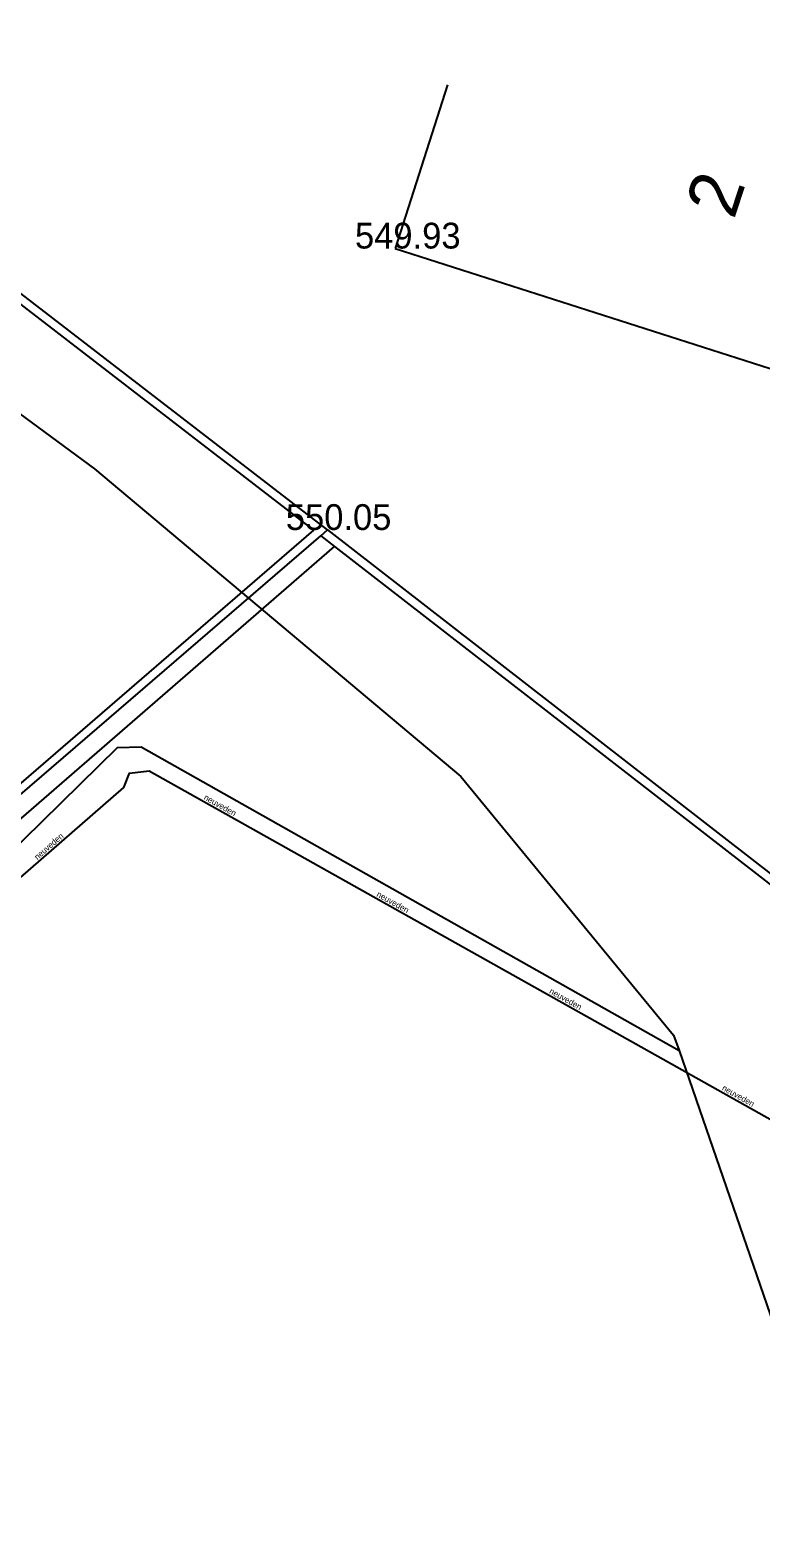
# Model space of a CAD drawing. Extents: x -669995 to -669686, y -1125551 to -1125263.
# Drawn here: x -669887.75 to -669866.53, y -1125464.59 to -1125420.77 of the extents above; entities that cross this region are included whole.
import ezdxf

# ---------------------------------------------------------------- set-up
doc = ezdxf.new("R2010")
doc.units = 0
for name, color, linetype in [('G_Bod_tecka', 7, 'Continuous'), ('G_Bod_vyska', 7, 'Continuous'), ('G_Budovy_Objekty', 7, 'Continuous'), ('G_Cisla_popisna', 7, 'Continuous'), ('G_Plochy_zpevnene', 7, 'Continuous'), ('G_Ploty', 7, 'Continuous'), ('G_Z_KANAL_podz_kotovane', 7, 'Continuous'), ('G_Z_SPOJE_podz_geodeticky', 7, 'Continuous'), ('G_Z_SPOJE_podz_kotovane', 7, 'Continuous'), ('G_Z_SPOJE_podz_priblizne', 7, 'Continuous'), ('Vrstva 13', 7, 'Continuous'), ('Vrstva 3', 7, 'Continuous')]:
    doc.layers.add(name, color=color, linetype=linetype)

msp = doc.modelspace()

# ---------------------------------------------------------------- linework, layer by layer
at = {"layer": 'G_Bod_tecka'}
for p, q in [((-669877.15, -1125427.12), (-669877.15, -1125427.12)), ((-669879.12, -1125435.3), (-669879.12, -1125435.3))]:
    msp.add_line(p, q, dxfattribs=at)
at = {"layer": 'G_Budovy_Objekty'}
for p, q in [((-669875.63, -1125422.36), (-669877.15, -1125427.12)), ((-669877.15, -1125427.12), (-669865.24, -1125430.93))]:
    msp.add_line(p, q, dxfattribs=at)
at = {"layer": 'G_Plochy_zpevnene'}
msp.add_line((-669890.97, -1125446.25), (-669878.91, -1125435.78), dxfattribs=at)
at = {"layer": 'G_Ploty'}
for p, q in [((-669879.12, -1125435.3), (-669920.7, -1125403.21)), ((-669920.66, -1125403.56), (-669879.52, -1125435.31)), ((-669879.52, -1125435.31), (-669905.49, -1125457.7)), ((-669905.22, -1125457.8), (-669879.31, -1125435.47)), ((-669879.31, -1125435.47), (-669879.12, -1125435.3)), ((-669879.31, -1125435.47), (-669878.91, -1125435.78)), ((-669878.91, -1125435.78), (-669859.03, -1125451.21))]:
    msp.add_line(p, q, dxfattribs=at)
msp.add_lwpolyline([(-669879.12, -1125435.3), (-669861.07, -1125449.31), (-669860.73, -1125449.57), (-669858.75, -1125451.11)], dxfattribs=at)
at = {"layer": 'G_Z_KANAL_podz_kotovane'}
for points in [[(-669898.38, -1125455.52), (-669897.15, -1125454.62), (-669893.45, -1125450.11), (-669885.03, -1125442.78), (-669884.87, -1125442.37)], [(-669884.87, -1125442.37), (-669884.3, -1125442.3), (-669865.39, -1125452.91), (-669865.02, -1125452.92), (-669859.66, -1125451.66), (-669859.5, -1125451.55)]]:
    msp.add_lwpolyline(points, dxfattribs=at)
at = {"layer": 'G_Z_SPOJE_podz_geodeticky'}
for points in [[(-669901.71, -1125421.87), (-669885.88, -1125433.52), (-669875.24, -1125442.46), (-669869.06, -1125449.98), (-669868.9, -1125450.43)], [(-669919.3, -1125436.71), (-669920.48, -1125456.12), (-669920.16, -1125456.28), (-669897.74, -1125453.92), (-669885.22, -1125441.62), (-669884.53, -1125441.6), (-669868.9, -1125450.43)], [(-669868.9, -1125450.43), (-669865.28, -1125460.94), (-669865.56, -1125476.2), (-669868.62, -1125490.28), (-669873.32, -1125500), (-669873.84, -1125501.08), (-669875.38, -1125507.75), (-669876.44, -1125519.45), (-669880.16, -1125533.89), (-669884.345, -1125547.846)]]:
    msp.add_lwpolyline(points, dxfattribs=at)
at = {"layer": 'G_Z_SPOJE_podz_kotovane'}
msp.add_lwpolyline([(-669919.3, -1125436.71), (-669920.48, -1125456.12), (-669920.16, -1125456.28), (-669897.74, -1125453.92), (-669885.22, -1125441.62), (-669884.53, -1125441.6), (-669868.9, -1125450.43)], dxfattribs=at)
at = {"layer": 'G_Z_SPOJE_podz_priblizne'}
msp.add_lwpolyline([(-669919.3, -1125436.71), (-669920.48, -1125456.12), (-669920.16, -1125456.28), (-669897.74, -1125453.92), (-669885.22, -1125441.62), (-669884.53, -1125441.6), (-669868.9, -1125450.43)], dxfattribs=at)
at = {"layer": 'Vrstva 13'}
for points in [[(-669898.384, -1125455.525), (-669897.15, -1125454.62), (-669893.45, -1125450.11), (-669885.03, -1125442.78), (-669884.87, -1125442.37)], [(-669885.03, -1125442.78), (-669884.87, -1125442.37), (-669884.3, -1125442.3), (-669865.39, -1125452.91), (-669865.02, -1125452.92), (-669859.66, -1125451.66), (-669859.5, -1125451.55)]]:
    msp.add_lwpolyline(points, dxfattribs=at)

# ---------------------------------------------------------------- texts
at = {"layer": 'G_Bod_vyska'}
for s, p in [('549.93', (-669878.318, -1125427.12)), ('550.05', (-669880.327, -1125435.3))]:
    msp.add_text(s, height=0.75, dxfattribs=at).set_placement(p)
at = {"layer": 'G_Cisla_popisna'}
msp.add_text('2', height=1.5, rotation=71.9483, dxfattribs=at).set_placement((-669867.309, -1125426.3))
at = {"layer": 'Vrstva 3'}
for rotation, p in [(330.7491, (-669882.726, -1125443.123)), (41.0235, (-669887.543, -1125444.899)), (330.6981, (-669877.708, -1125445.939)), (330.7124, (-669872.69, -1125448.753)), (330.6694, (-669867.673, -1125451.568))]:
    msp.add_text('neuveden', height=0.1755, rotation=rotation, dxfattribs=at).set_placement(p)

doc.saveas('drawing.dxf')
